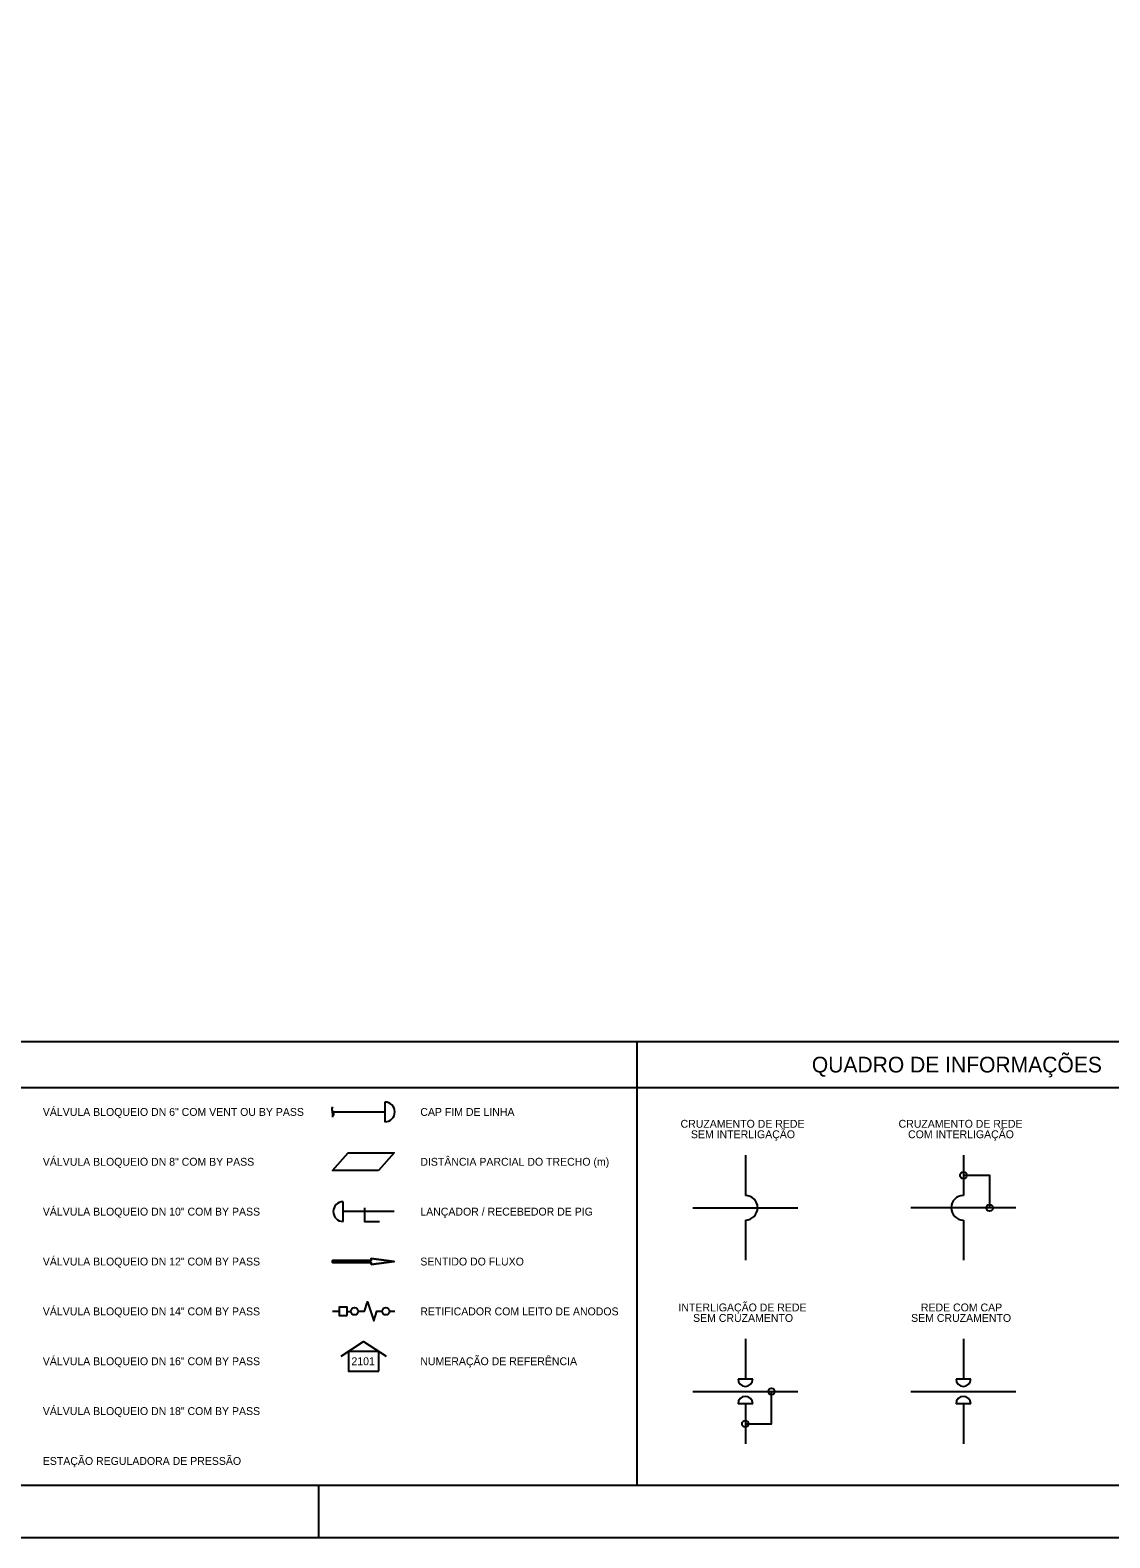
# Model space of a CAD drawing. Extents: x -1349 to -508, y 286 to 880.
# Drawn here: x -933.1 to -727.3, y 285.8 to 573.1 of the extents above; entities that cross this region are included whole.
import ezdxf

# ---------------------------------------------------------------- set-up
doc = ezdxf.new("R2010")
doc.units = 0
doc.layers.add('FORMATO', color=7, linetype='Continuous')
doc.layers.add('LEGENDA', color=7, linetype='Continuous')

msp = doc.modelspace()

# ---------------------------------------------------------------- linework, layer by layer
at = {"layer": 'FORMATO'}
msp.add_line((-518.04, 295.82), (-1344.05, 295.82), dxfattribs=at)
msp.add_lwpolyline([(-1349.05, 879.82), (-508.05, 879.82), (-508.05, 285.82), (-1349.05, 285.82)], close=True, dxfattribs=at)
for points in [[(-518.04, 380.36), (-1324.05, 380.36)], [(-817.42, 295.82), (-817.42, 380.36)], [(-1324.05, 371.63), (-693.05, 371.63)], [(-878.05, 285.82), (-878.05, 295.82)]]:
    msp.add_lwpolyline(points, dxfattribs=at)
at = {"layer": 'LEGENDA'}
for p, q in [((-863.72, 338.47), (-868.11, 339.04)), ((-868.11, 339.04), (-868.11, 338.66)), ((-868.11, 338.66), (-875.45, 338.66)), ((-875.45, 338.66), (-875.45, 338.29)), ((-875.45, 338.29), (-868.11, 338.29)), ((-868.11, 337.91), (-863.72, 338.47)), ((-868.11, 338.29), (-868.11, 337.91))]:
    msp.add_line(p, q, dxfattribs=at)
for points in [[(-865.46, 368.85), (-865.46, 365.1)], [(-875.45, 366.98), (-865.46, 366.98)], [(-796.78, 358.72), (-796.78, 351.07)], [(-755.23, 358.72), (-755.23, 351.07)], [(-755.23, 354.9), (-750.23, 354.9), (-750.23, 348.72)], [(-873.43, 346.1), (-873.43, 349.85)], [(-863.72, 347.98), (-873.43, 347.98)], [(-869.35, 348.69), (-869.35, 346.1), (-866.48, 346.1)], [(-806.78, 348.72), (-786.78, 348.72)], [(-745.23, 348.72), (-765.23, 348.72)], [(-796.78, 346.38), (-796.78, 338.72)], [(-755.23, 346.38), (-755.23, 338.72)], [(-870.56, 329), (-869.38, 329), (-868.78, 330.8), (-867.58, 327.19), (-866.98, 329), (-865.98, 329)], [(-874.21, 328.98), (-875.45, 328.98)], [(-872.67, 328.21), (-872.67, 329.75), (-874.21, 329.75), (-874.21, 328.21), (-872.67, 328.21)], [(-872.67, 328.98), (-871.97, 328.98)], [(-864.58, 329), (-863.59, 329)], [(-873.83, 320.41), (-869.52, 323.22), (-865.2, 320.41)], [(-796.78, 323.72), (-796.78, 316.07)], [(-755.23, 323.72), (-755.23, 316.07)], [(-795.38, 316.07), (-798.18, 316.07)], [(-753.83, 316.07), (-756.63, 316.07)], [(-806.78, 313.72), (-786.78, 313.72)], [(-796.78, 307.55), (-791.78, 307.55), (-791.78, 313.72)], [(-765.23, 313.72), (-745.23, 313.72)], [(-795.38, 311.38), (-798.18, 311.38)], [(-796.78, 311.38), (-796.78, 303.72)], [(-753.83, 311.38), (-756.63, 311.38)], [(-755.23, 311.38), (-755.23, 303.72)]]:
    msp.add_lwpolyline(points, dxfattribs=at)
for points in [[(-866.72, 355.79), (-875.45, 355.79), (-872.45, 359.16), (-863.72, 359.16)], [(-868.11, 337.91), (-868.11, 338.29), (-875.45, 338.29), (-875.45, 338.66), (-868.11, 338.66), (-868.11, 339.04), (-863.72, 338.47)], [(-866.64, 317.6), (-866.64, 321.35), (-872.39, 321.35), (-872.39, 317.6)]]:
    msp.add_lwpolyline(points, close=True, dxfattribs=at)
for centre, radius in [((-755.23, 354.9), 0.633), ((-750.23, 348.72), 0.633), ((-871.27, 328.99), 0.701), ((-865.28, 328.99), 0.701), ((-791.78, 313.72), 0.633), ((-796.78, 307.55), 0.633)]:
    msp.add_circle(centre, radius, dxfattribs=at)
for centre, radius, start, end in [((-865.46, 366.98), 1.88, 270, 90), ((-796.78, 348.72), 2.34, 270, 90), ((-755.23, 348.72), 2.34, 90, 270), ((-873.43, 347.98), 1.88, 90, 270), ((-796.78, 316.07), 1.4, 180, 0), ((-755.23, 316.07), 1.4, 180, 0), ((-796.78, 311.38), 1.4, 0, 180), ((-755.23, 311.38), 1.4, 0, 180)]:
    msp.add_arc(centre, radius, start, end, dxfattribs=at)
msp.add_open_spline([(-875.45, 367.98), (-875.7, 367.48), (-875.45, 366.98), (-875.2, 366.48), (-875.45, 365.98), (-875.45, 367.98), (-875.45, 365.98)], degree=3, dxfattribs=at)

# ---------------------------------------------------------------- texts
at = {"layer": 'FORMATO'}
msp.add_text('QUADRO DE INFORMAÇÕES', height=3, rotation=360, dxfattribs=at).set_placement((-784.11, 374.5))
at = {"layer": 'LEGENDA'}
for s, p in [('VÁLVULA BLOQUEIO DN 6" COM VENT OU BY PASS', (-930.66, 366.23)), ('CAP FIM DE LINHA', (-858.72, 366.23)), ('CRUZAMENTO DE REDE', (-809.13, 363.97)), ('CRUZAMENTO DE REDE', (-767.58, 363.97)), ('SEM INTERLIGAÇÃO', (-807.15, 361.97)), ('COM INTERLIGAÇÃO', (-765.77, 361.97)), ('VÁLVULA BLOQUEIO DN 8" COM BY PASS', (-930.66, 356.73)), ('DISTÂNCIA PARCIAL DO TRECHO (m)', (-858.72, 356.73)), ('VÁLVULA BLOQUEIO DN 10" COM BY PASS', (-930.66, 347.23)), ('LANÇADOR / RECEBEDOR DE PIG', (-858.72, 347.23)), ('VÁLVULA BLOQUEIO DN 12" COM BY PASS', (-930.66, 337.72)), ('SENTIDO DO FLUXO', (-858.72, 337.72)), ('INTERLIGAÇÃO DE REDE', (-809.53, 328.97)), ('REDE COM CAP', (-763.33, 328.97)), ('VÁLVULA BLOQUEIO DN 14" COM BY PASS', (-930.66, 328.22)), ('RETIFICADOR COM LEITO DE ANODOS', (-858.72, 328.22)), ('SEM CRUZAMENTO', (-806.74, 326.97)), ('SEM CRUZAMENTO', (-765.19, 326.97)), ('VÁLVULA BLOQUEIO DN 16" COM BY PASS', (-930.66, 318.72)), ('2101', (-871.85, 318.72)), ('NUMERAÇÃO DE REFERÊNCIA', (-858.72, 318.72)), ('VÁLVULA BLOQUEIO DN 18" COM BY PASS', (-930.66, 309.22)), ('ESTAÇÃO REGULADORA DE PRESSÃO', (-930.66, 299.72))]:
    msp.add_text(s, height=1.5, dxfattribs=at).set_placement(p)

doc.saveas('drawing.dxf')
